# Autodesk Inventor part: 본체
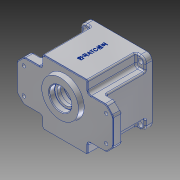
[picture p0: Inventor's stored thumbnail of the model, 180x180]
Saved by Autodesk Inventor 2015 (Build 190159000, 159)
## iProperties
Created: 2016-02
Part Number: 본체
Material: Aluminum 6061
Document SubType Name: Modeling
Designer: Administrator
Density: 2.7 g/cm^3
Appearance: Aluminum - Flat
Mass: 874.065 g
Surface Area: 762.671 cm^2
Volume: 323.728 cm^3
Author: Administrator
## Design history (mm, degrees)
sketch "Sketch1"
  geometry: L1 (47, -47)-(-47, -47); L2 (-47, -47)-(-47, 47); L3 (-47, 47)-(47, 47); L4 (47, 47)-(47, -47); L5 (47, -47)-(-47, 47); L6 (-47, -47)-(47, 47); 1 further point
  constraints: 12 end point, 2 midpoint, 2 parallel, 1 horizontal, 1 perpendicular
  dimensions: "d0" = 94 distance of L2.end L3.end; "d1" = 94 distance of L1.end L2.end
extrude "Extrusion1" new body sketch "Sketch1" distance "d2" = 10; taper "d3" = 0 deg
sketch "Sketch2"
  geometry: L1 (33, -47)-(-33, -47); L2 (-33, -47)-(-33, 47); L3 (-33, 47)-(33, 47); L4 (33, 47)-(33, -47); L5 (33, -47)-(-33, 47); L6 (-33, -47)-(33, 47); L7 (47, 30)-(-47, 30); L8 (-47, 30)-(-47, -30); L9 (-47, -30)-(47, -30); L10 (47, -30)-(47, 30); L11 (47, 30)-(-47, -30); L12 (-47, 30)-(47, -30); 1 further point
  constraints: 24 end point, 4 midpoint, 4 parallel, 2 horizontal, 2 perpendicular
  dimensions: "d4" = 66 distance of L2.end L3.end; "d5" = 94 distance of L1.end L2.end; "d6" = 94 distance of L9.end L8.end; "d7" = 60 distance of L9.end L7.start
extrude "Extrusion2" join sketch "Sketch2" distance "d8" = 57; taper "d9" = 0 deg
sketch "Sketch3"
  geometry: L1 (70, -30)-(-70, -30); L2 (-70, -30)-(-70, 30); L3 (-70, 30)-(70, 30); L4 (70, 30)-(70, -30); L5 (70, -30)-(-70, 30); L6 (-70, -30)-(70, 30); L7 (33, -47)-(-33, -47); L8 (-33, -47)-(-33, 47); L9 (-33, 47)-(33, 47); L10 (33, 47)-(33, -47); L11 (33, -47)-(-33, 47); L12 (-33, -47)-(33, 47); 1 further point
  constraints: 24 end point, 4 midpoint, 4 parallel, 2 horizontal, 2 perpendicular
  dimensions: "d10" = 140 distance of L2.end L3.end; "d11" = 60 distance of L1.end L2.end; "d12" = 66 distance of L8.end L9.end; "d13" = 94 distance of L7.end L8.end
extrude "Extrusion3" join sketch "Sketch3" distance "d14" = 13; taper "d15" = 0 deg
sketch "Sketch4"
  geometry: C1 r 43 at (0, 0); 1 further point
  constraints: 1 centre point, 1 coincident
  dimensions: "d16" = 86 diameter of C1
extrude "Extrusion4" cut sketch "Sketch4" distance "d17" = 9; taper "d18" = 0 deg
hole "Hole1" diameter "d21" = 80; stored, may be unused: countersink angle "d25" = 90 deg, drill point angle "d27" = 0 deg; dims "d19" = 10, "d20" = 10, "d22" = 6, "d23" = 4, "d24" = 2, "d26" = 62
chamfer "Chamfer1" distance "d28" = 10; stored, may be unused: second distance "d29" = 2, angle "d30" = 45 deg
sketch "Sketch5"
  geometry: C1 r 28 at (0, -11); 1 further point
  constraints: 1 centre point, 1 vertical alignment
  dimensions: "d31" = 56 diameter of C1; "d32" = 11 distance of C1.centre point (0, 0)
extrude "Extrusion5" join sketch "Sketch5" distance "d33" = 7; taper "d34" = -10 deg
hole "Hole2" diameter "d37" = 32; stored, may be unused: countersink angle "d41" = 90 deg, drill point angle "d43" = 0 deg; dims "d35" = 10, "d36" = 10, "d38" = 6, "d39" = 4, "d40" = 2, "d42" = 8
hole "Hole3" diameter "d46" = 25; stored, may be unused: countersink angle "d50" = 90 deg, drill point angle "d52" = 0 deg; dims "d44" = 10, "d45" = 10, "d47" = 6, "d48" = 4, "d49" = 2, "d51" = 5
hole "Hole4" diameter "d55" = 35; stored, may be unused: countersink angle "d59" = 90 deg, drill point angle "d61" = 0 deg; dims "d53" = 10, "d54" = 10, "d56" = 6, "d57" = 4, "d58" = 2, "d60" = 10
sketch "Sketch6"
  geometry: C1 r 21 at (0, -11); A1 r 17.5 centre (0, -11) between (-4.864, 5.81) and (4.864, 5.81) reference; A2 r 15 centre (0, 20) between (4.864, 5.81) and (-4.864, 5.81); 1 further point
  constraints: 4 point on circle, 2 centre point, 1 coincident, 1 vertical alignment
  dimensions: "d62" = 21 radius of C1; "d63" = 15 radius of A2; "d64" = 20 distance of point (0, 0) A2.centre
extrude "Extrusion6" join sketch "Sketch6" distance "d65" = 7; taper "d66" = 0 deg
hole "Hole5" diameter "d69" = 22; stored, may be unused: countersink angle "d73" = 90 deg, drill point angle "d75" = 0 deg; dims "d67" = 10, "d68" = 10, "d70" = 6, "d71" = 4, "d72" = 2, "d74" = 7
hole "Hole6" diameter "d78" = 19; stored, may be unused: countersink angle "d82" = 90 deg, drill point angle "d84" = 0 deg; dims "d76" = 10, "d77" = 10, "d79" = 6, "d80" = 4, "d81" = 2, "d83" = 1
sketch "Sketch7"
  geometry: L1 (39.799, 4)-(35.777, 4); L2 (-35.777, 4)-(-39.799, 4); L3 (39.799, -4)-(35.777, -4); L4 (-35.777, -4)-(-39.799, -4); A1 r 36 centre (0, 0) between (36, 0) and (-36, 0); A2 r 4 centre (36, 0) between (36, 4) and (36, -4); A3 r 4 centre (-36, 0) between (-36, -4) and (-36, 4); A4 r 40 centre (0, 0) between (39.799, -4) and (39.799, 4) reference; 1 further point
  constraints: 14 point on circle, 8 end point, 4 horizontal, 4 point on line, 4 tangent, 3 centre point, 2 horizontal alignment, 1 coincident
  dimensions: "d85" = 36 radius of A1; "d86" = 4 radius of A2; "d87" = 4 radius of A3
extrude "Extrusion7" join sketch "Sketch7" stored distance "d88" = 7; taper "d89" = 0 deg
fillet "Fillet1" dims "d90" = 3.5
sketch "Sketch9"
  geometry: L1 (60, -19)-(-60, -19); L2 (-60, -19)-(-60, 19); L3 (-60, 19)-(60, 19); L4 (60, 19)-(60, -19); L5 (60, -19)-(-60, 19); L6 (-60, -19)-(60, 19); 5 further points
  constraints: 12 end point, 4 coincident, 2 midpoint, 2 parallel, 1 horizontal, 1 perpendicular
  dimensions: "d93" = 120 distance of L2.end L3.end; "d94" = 38 distance of L1.end L2.end
hole "Hole7" sketch "Sketch9" at (-60, 19), (-60, -19), (60, -19), (60, 19) diameter "d95" = 5; stored, may be unused: countersink angle "d99" = 90 deg, drill point angle "d101" = 0 deg; dims "d96" = 6, "d97" = 9, "d98" = 4, "d100" = 13
sketch "Sketch10"
  geometry: L1 (60, 30)-(70, 20) reference; L2 (60, 30)-(33, 30) reference; L3 (33, 30)-(33, 47) reference; L4 (33, 47)-(-33, 47) reference; L5 (-33, 47)-(-33, 30) reference; L6 (-33, 30)-(-60, 30) reference; L7 (-70, 20)-(-60, 30) reference; L8 (-70, 20)-(-70, -20) reference; L9 (-60, -30)-(-70, -20) reference; L10 (-60, -30)-(-33, -30) reference; L11 (-33, -30)-(-33, -47) reference; L12 (-33, -47)-(33, -47) reference; L13 (33, -47)-(33, -30) reference; L14 (33, -30)-(60, -30) reference; L15 (70, -20)-(60, -30) reference; L16 (70, -20)-(70, 20) reference; L17 (59.586, -29)-(32, -29); L18 (32, -29)-(32, -46); L19 (32, -46)-(-32, -46); L20 (-32, -46)-(-32, -29); L21 (-32, -29)-(-59.586, -29); L22 (-59.586, -29)-(-69, -19.586); L23 (-69, -19.586)-(-69, 19.586); L24 (-69, 19.586)-(-59.586, 29); L25 (-59.586, 29)-(-32, 29); L26 (-32, 29)-(-32, 46); L27 (-32, 46)-(32, 46); L28 (32, 46)-(32, 29); L29 (32, 29)-(59.586, 29); L30 (59.586, 29)-(69, 19.586); L31 (69, 19.586)-(69, -19.586); L32 (69, -19.586)-(59.586, -29); C1 r 2.5 at (-60, -19) reference; C2 r 2.5 at (60, 19) reference; C3 r 2.5 at (60, -19) reference; C4 r 2.5 at (-60, 19) reference; C5 r 28 at (0, -11) reference; 1 further point
  constraints: 32 end point, 15 other
  dimensions: "d102" = 1 distance between parallel lines of L14 L17
extrude "Extrusion8" cut sketch "Sketch10" distance "d103" = 1; taper "d104" = 0 deg
fillet "Fillet2" dims "d105" = 5
fillet "Fillet3" dims "d106" = 8
fillet "Fillet4" dims "d107" = 3
sketch "Sketch11"
  geometry: L1 (72, -79)-(-6, -79) reference; 3 further points
  constraints: 1 midpoint, 1 vertical alignment, 1 other
  dimensions: "d132" = 40 distance of point (33, -79) point (33, -39)
emboss "Emboss1" sketch "Sketch11" dims "d0" = 94, "d1" = 94, "d108" = 0.5, "d109" = 0
fillet "Fillet5" dims "d110" = 2
fillet "Fillet6" dims "d111" = 2
fillet "Fillet7" dims "d112" = 0.3
chamfer "Chamfer2" distance "d113" = 1; stored, may be unused: second distance "d114" = 2, angle "d115" = 45 deg
sketch "Sketch12"
  geometry: L1 (-40, 40)-(40, 40); L2 (40, 40)-(40, -40); L3 (40, -40)-(-40, -40); L4 (-40, -40)-(-40, 40); L5 (-40, 40)-(40, -40); L6 (40, 40)-(-40, -40); 5 further points
  constraints: 12 end point, 3 coincident, 2 midpoint, 2 parallel, 1 horizontal, 1 perpendicular
  dimensions: "d116" = 80 distance of L2.end L3.end; "d117" = 80 distance of L1.end L2.end
hole "Hole8" sketch "Sketch12" at (40, -40), (40, 40), (-40, 40), (-40, -40) diameter "d118" = 7; stored, may be unused: countersink angle "d122" = 90 deg, drill point angle "d124" = 0 deg; dims "d119" = 6, "d120" = 9, "d121" = 4, "d123" = 13
sketch "Sketch13"
  geometry: A1 r 4 centre (-36, 0) between (-35.778, -3.994) and (-35.778, 3.994) reference; A2 r 4 centre (36, 0) between (35.778, 3.994) and (35.778, -3.994) reference; 3 further points
  constraints: 2 coincident
hole "Hole9" sketch "Sketch13" at (-36, 0), (36, 0) diameter "d125" = 3.242; stored, may be unused: countersink angle "d129" = 90 deg, drill point angle "d131" = 118 deg; dims "d126" = 7, "d127" = 9, "d128" = 4, "d130" = 9
body "Solid1"
node "Projected Loop1"
